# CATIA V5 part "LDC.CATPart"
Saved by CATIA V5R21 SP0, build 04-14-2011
Part number: LDC.SLDPRT
Bounding box of the stored display mesh (mm): x -1.7 to 1.7, y -1.65 to 1.65, z -1.105 to 0.8
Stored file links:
  C:\Users\user\Desktop\CATIA文件\0-最新文件\LDC\LDC.CATPart
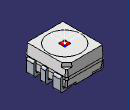
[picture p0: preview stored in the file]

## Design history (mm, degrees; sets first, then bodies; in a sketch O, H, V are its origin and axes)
AxisSystem1: origin (-0.0013, 0.0024, 0.8), X (-1, 0, 0), Y (0, -1, 0), Z (0, 0, 1)
Set1
  DatumSurface1 to DatumSurface139
  Circle1: stored without definition
  Circle2: stored without definition
  DatumCurve1 to DatumCurve5
  Line1 to Line5: stored without definition
  DatumCurve6 to DatumCurve12
  Line6: stored without definition
  Circle3 to Circle8: stored without definition
  Line7: stored without definition
  Circle9: stored without definition
  Line8: stored without definition
  Circle10: stored without definition
  Line9: stored without definition
  Circle11: stored without definition
  Line10: stored without definition
  Circle12: stored without definition
  Line11 to Line13: stored without definition
  Circle13: stored without definition
  Line14: stored without definition
  Circle14: stored without definition
  Line15 to Line23: stored without definition
  Circle15: stored without definition
  Line24: stored without definition
  Circle16: stored without definition
  Line25 to Line27: stored without definition
  Circle17: stored without definition
  Line28: stored without definition
  Circle18: stored without definition
  Line29 to Line40: stored without definition
  Circle19: stored without definition
  Line41: stored without definition
  Circle20: stored without definition
  Line42 to Line44: stored without definition
  Circle21: stored without definition
  Line45: stored without definition
  Circle22: stored without definition
  Line46 to Line54: stored without definition
  Circle23: stored without definition
  Line55: stored without definition
  Circle24: stored without definition
  Line56 to Line58: stored without definition
  Circle25: stored without definition
  Line59: stored without definition
  Circle26: stored without definition
  Line60 to Line65: stored without definition
  Circle27 to Circle29: stored without definition
  Line66: stored without definition
  Circle30: stored without definition
  Line67: stored without definition
  Circle31: stored without definition
  Line68: stored without definition
  Circle32: stored without definition
  Line69: stored without definition
  Circle33 to Circle38: stored without definition
  Line70: stored without definition
  Line71: stored without definition
  Circle39: stored without definition
  Circle40: stored without definition
  Line72 to Line78: stored without definition
  DatumCurve13
  DatumCurve14
  Line79: stored without definition
  Line80: stored without definition
  Circle41: stored without definition
  Line81: stored without definition
  DatumCurve15
  Line82: stored without definition
  Line83: stored without definition
  DatumCurve16
  Line84: stored without definition
  Circle42: stored without definition
  Line85: stored without definition
  DatumCurve17
  Line86: stored without definition
  DatumCurve18
  Line87 to Line89: stored without definition
  DatumCurve19
  DatumCurve20
  Line90: stored without definition
  Circle43: stored without definition
  Line91: stored without definition
  Circle44: stored without definition
  Circle45: stored without definition
  Line92: stored without definition
  Circle46 to Circle49: stored without definition
  Line93: stored without definition
  Circle50: stored without definition
  Line94 to Line99: stored without definition
  DatumCurve21
  Line100: stored without definition
  Circle51: stored without definition
  Line101: stored without definition
  Line102: stored without definition
  DatumCurve22
  Line103 to Line111: stored without definition
  DatumCurve23
  Line112: stored without definition
  DatumCurve24
  Line113: stored without definition
  Circle52: stored without definition
  DatumCurve25
  Line114 to Line116: stored without definition
  Circle53: stored without definition
  Line117 to Line124: stored without definition
  DatumCurve26
  Line125: stored without definition
  DatumCurve27 to DatumCurve29
  Circle54: stored without definition
  Line126: stored without definition
  Circle55: stored without definition
  Line127 to Line129: stored without definition
  DatumCurve30
  Line130: stored without definition
  Line131: stored without definition
  DatumCurve31
  Line132 to Line139: stored without definition
  DatumCurve32
  Line140 to Line143: stored without definition
  DatumCurve33
  Line144 to Line169: stored without definition
  Circle56: stored without definition
  Line170: stored without definition
  Circle57: stored without definition
  Line171 to Line173: stored without definition
  Circle58: stored without definition
  Line174: stored without definition
  Circle59: stored without definition
  Line175 to Line183: stored without definition
  Circle60: stored without definition
  Line184: stored without definition
  Circle61: stored without definition
  Line185 to Line187: stored without definition
  Circle62: stored without definition
  Circle63: stored without definition
  Line188: stored without definition
  Circle64: stored without definition
  Circle65: stored without definition
  Line189 to Line191: stored without definition
  Circle66: stored without definition
  Line192: stored without definition
  Circle67: stored without definition
  Line193 to Line201: stored without definition
  Circle68: stored without definition
  Line202: stored without definition
  Circle69: stored without definition
  Line203 to Line205: stored without definition
  Circle70: stored without definition
  Line206: stored without definition
  Circle71: stored without definition
  Line207: stored without definition
  Line208: stored without definition
  Circle72: stored without definition
  Line209: stored without definition
  Circle73: stored without definition
  Line210 to Line212: stored without definition
  Circle74: stored without definition
  Line213: stored without definition
  Circle75: stored without definition
  Line214 to Line216: stored without definition
  Circle76: stored without definition
  Line217 to Line219: stored without definition
  Circle77: stored without definition
  Line220 to Line227: stored without definition
  Circle78: stored without definition
  Line228: stored without definition
  Line229: stored without definition
  Circle79: stored without definition
  Line230: stored without definition
  Circle80: stored without definition
  Line231: stored without definition
  Circle81: stored without definition
  Line232 to Line234: stored without definition
  Circle82: stored without definition
  Line235: stored without definition
  Circle83: stored without definition
  Line236: stored without definition
  Circle84: stored without definition
  Line237 to Line239: stored without definition
  Circle85: stored without definition
  Line240 to Line245: stored without definition
  Circle86: stored without definition
  Line246 to Line248: stored without definition
  Circle87: stored without definition
  Line249: stored without definition
  Line250: stored without definition
  Circle88: stored without definition
  Line251 to Line258: stored without definition
  Point1 "几何中心&发光中心（测试原点）": type Center, Curve edge of DatumSurface70
  Point2 "虚拟坐标": (0.016, -0.002, -0.192), relative to Point1, in AxisSystem1
Body1 (main body)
